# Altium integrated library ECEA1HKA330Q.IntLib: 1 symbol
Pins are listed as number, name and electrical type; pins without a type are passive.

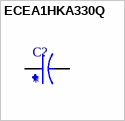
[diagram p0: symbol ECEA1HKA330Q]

## ECEA1HKA330Q
designator C?
CAP ALUM 33UF 20% 50V RADIAL; MF: Panasonic; MP: ECE-A1HKA330Q
footprint CAPPRD500W45D800H700
pins: N, P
